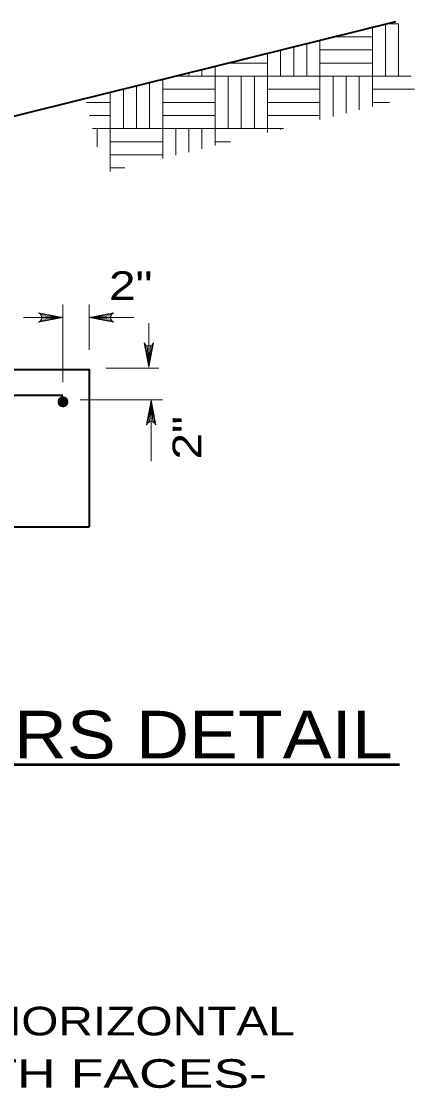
# Model space of a CAD drawing. Extents: x 394.95 to 401.96, y -76.51 to -66.78.
# Drawn here: x 400.292 to 401.117, y -69.196 to -66.946 of the extents above; entities that cross this region are included whole.
import ezdxf
from ezdxf.enums import TextEntityAlignment as Align

# ---------------------------------------------------------------- set-up
doc = ezdxf.new("R2010")
doc.units = 0
doc.header["$LTSCALE"] = 0.024
doc.linetypes.add('LONG_DASHED', pattern=[7.5, 6, -1.5])
for name, color, linetype, lineweight in [('1', 7, 'LONG_DASHED', 35), ('10', 7, 'Continuous', 13), ('13', 7, 'Continuous', 25), ('6', 7, 'Continuous', 13)]:
    doc.layers.add(name, color=color, linetype=linetype, lineweight=lineweight)
doc.layers.add('12', color=7, linetype='Continuous')

msp = doc.modelspace()

# ---------------------------------------------------------------- linework, layer by layer
at = {"layer": '1', "linetype": 'Continuous'}
for p, q in [((400.15918, -67.17381), (401.07785, -66.94648)), ((399.38918, -68.0064), (400.43418, -68.0064))]:
    msp.add_line(p, q, dxfattribs=at)
at = {"layer": '1', "linetype": 'Continuous', "lineweight": 13}
for p, q in [((400.69841, -67.06135), (400.69841, -67.04036)), ((400.61591, -67.06135), (400.61591, -67.06079))]:
    msp.add_line(p, q, dxfattribs=at)
at = {"layer": '1'}
msp.add_line((400.37918, -67.7314), (399.74668, -67.7314), dxfattribs=at)
at = {"layer": '1', "linetype": 'Continuous'}
msp.add_lwpolyline([(400.15918, -67.6764), (400.43418, -67.6764), (400.43418, -68.0064)], dxfattribs=at)
at = {"layer": '1', "lineweight": 13}
for points in [[(400.37644, -67.7349), (400.37965, -67.73433), (400.38343, -67.73546), (400.38741, -67.73895), (400.3888, -67.74228), (400.38884, -67.74629), (400.38675, -67.7508), (400.38375, -67.75345), (400.38042, -67.75428), (400.37665, -67.75417), (400.3734, -67.75259), (400.37118, -67.75055), (400.36978, -67.74746), (400.36912, -67.74401), (400.36998, -67.74079), (400.37158, -67.73806), (400.3742, -67.73591), (400.37644, -67.73497), (400.3823, -67.73502), (400.37527, -67.73542), (400.38367, -67.73546), (400.37343, -67.73602), (400.38482, -67.73622), (400.37295, -67.73666), (400.38547, -67.73674), (400.37227, -67.73719), (400.38627, -67.73743), (400.37162, -67.73779), (400.38687, -67.73795), (400.3713, -67.73839), (400.38711, -67.73847), (400.37085, -67.73883), (400.38768, -67.73895), (400.37061, -67.73916), (400.38784, -67.73943), (400.37043, -67.73967), (400.38813, -67.7398), (400.37022, -67.74007), (400.38836, -67.74023), (400.36966, -67.74064), (400.38853, -67.74064), (400.36957, -67.74124), (400.38865, -67.74096), (400.36945, -67.74192), (400.38884, -67.74159), (400.36921, -67.74269), (400.38889, -67.74213), (400.36933, -67.74236), (400.38912, -67.7426), (400.36918, -67.74317), (400.38909, -67.74314), (400.36909, -67.74361), (400.38921, -67.74353), (400.36905, -67.74405), (400.38921, -67.74389), (400.36918, -67.74469), (400.38921, -67.74436), (400.36909, -67.74517), (400.38933, -67.7449), (400.36901, -67.74442), (400.38921, -67.74533), (400.36912, -67.74557), (400.38928, -67.74578), (400.36918, -67.74602), (400.38909, -67.74626), (400.36925, -67.74642), (400.38896, -67.74666), (400.36942, -67.74694), (400.38889, -67.74702), (400.3695, -67.74739), (400.3888, -67.7475), (400.36981, -67.7479), (400.38872, -67.74795), (400.3699, -67.74834), (400.38853, -67.74826), (400.37002, -67.74882), (400.38829, -67.74867), (400.37034, -67.74927), (400.38816, -67.74915), (400.37058, -67.74968), (400.38789, -67.74959), (400.3707, -67.75003), (400.3876, -67.75011), (400.37102, -67.75043), (400.38735, -67.75048), (400.37134, -67.75075), (400.38692, -67.75096), (400.37182, -67.75128), (400.38635, -67.75144), (400.3723, -67.75184), (400.38575, -67.75196), (400.37299, -67.75252), (400.38531, -67.75235), (400.37423, -67.75316), (400.38487, -67.75292), (400.37387, -67.75292), (400.38419, -67.75328), (400.37468, -67.75345), (400.3833, -67.75372), (400.37531, -67.75376), (400.3823, -67.75408)], [(400.3823, -67.75408), (400.37873, -67.75452), (400.37343, -67.75107), (400.37019, -67.74397), (400.37495, -67.73594), (400.38191, -67.7351), (400.38728, -67.74127), (400.38728, -67.7479), (400.38391, -67.7528), (400.37833, -67.75387), (400.37203, -67.75059), (400.37431, -67.75248), (400.3703, -67.74196), (400.37406, -67.73615), (400.37961, -67.73454), (400.38371, -67.73639), (400.38716, -67.7404), (400.38869, -67.7437), (400.38687, -67.75016)]]:
    msp.add_lwpolyline(points, dxfattribs=at)
msp.add_circle((400.37918, -67.74445), 0.01031, dxfattribs=at)
at = {"layer": '10'}
for p, q in [((400.37918, -67.7032), (400.37918, -67.54021)), ((400.43418, -67.63515), (400.43418, -67.54021)), ((400.29668, -67.56771), (400.37918, -67.56771)), ((400.43418, -67.56771), (400.52855, -67.56771)), ((400.55951, -67.57941), (400.55951, -67.67194)), ((400.46942, -67.67409), (400.58059, -67.67409)), ((400.41501, -67.74039), (400.5877, -67.74039)), ((400.56425, -67.74125), (400.56441, -67.86873))]:
    msp.add_line(p, q, dxfattribs=at)
for points in [[(400.37918, -67.56771), (400.32792, -67.5773), (400.33186, -67.57458), (400.33391, -67.57115), (400.33449, -67.56771), (400.33391, -67.56427), (400.33186, -67.56083), (400.32792, -67.55809), (400.37918, -67.56771), (400.33186, -67.56083), (400.33391, -67.56427), (400.37918, -67.56771), (400.33449, -67.56771), (400.33391, -67.57115), (400.37918, -67.56771), (400.33186, -67.57458)], [(400.43418, -67.56771), (400.48544, -67.55809), (400.48149, -67.56083), (400.47946, -67.56427), (400.47886, -67.56771), (400.47946, -67.57115), (400.48149, -67.57458), (400.48544, -67.5773), (400.43418, -67.56771), (400.48149, -67.57458), (400.47946, -67.57115), (400.43418, -67.56771), (400.47886, -67.56771), (400.47946, -67.56427), (400.43418, -67.56771), (400.48149, -67.56083)], [(400.43418, -67.56771), (400.48544, -67.55809), (400.48149, -67.56083), (400.47946, -67.56427), (400.47886, -67.56771), (400.47946, -67.57115), (400.48149, -67.57458), (400.48544, -67.5773), (400.43418, -67.56771), (400.48149, -67.57458), (400.47946, -67.57115), (400.43418, -67.56771), (400.47886, -67.56771), (400.47946, -67.56427), (400.43418, -67.56771), (400.48149, -67.56083)], [(400.55951, -67.67194), (400.5499, -67.62068), (400.55264, -67.62464), (400.55607, -67.62666), (400.55951, -67.62725), (400.56295, -67.62666), (400.56639, -67.62464), (400.56911, -67.62068), (400.55951, -67.67194), (400.56639, -67.62464), (400.56295, -67.62666), (400.55951, -67.67194), (400.55951, -67.62725), (400.55607, -67.62666), (400.55951, -67.67194), (400.55264, -67.62464)], [(400.56425, -67.74125), (400.57385, -67.79252), (400.57112, -67.78856), (400.56769, -67.78652), (400.56425, -67.78594), (400.56081, -67.78652), (400.55737, -67.78856), (400.55464, -67.79252), (400.56425, -67.74125), (400.55737, -67.78856), (400.56081, -67.78652), (400.56425, -67.74125), (400.56425, -67.78594), (400.56769, -67.78652), (400.56425, -67.74125), (400.57112, -67.78856)]]:
    msp.add_lwpolyline(points, dxfattribs=at)
at = {"layer": '13', "lineweight": 53}
msp.add_line((398.77915, -68.50517), (401.08564, -68.50517), dxfattribs=at)
at = {"layer": '6'}
for p, q in [((401.05591, -67.06135), (401.05591, -66.95191)), ((401.05818, -66.95135), (401.08299, -66.95135)), ((401.08341, -67.06135), (401.08341, -66.95302)), ((400.94705, -66.97885), (401.02841, -66.97885)), ((401.02841, -67.06135), (401.02841, -66.95871)), ((400.86341, -67.06135), (400.86341, -66.99954)), ((400.89091, -67.06135), (400.89091, -66.99274)), ((400.80841, -67.06135), (400.80841, -67.01316)), ((400.83591, -67.06135), (400.83591, -67.00635)), ((400.91841, -67.00635), (401.02841, -67.00635)), ((400.67091, -67.06135), (400.67091, -67.04718)), ((400.72479, -67.03385), (400.80841, -67.03385)), ((400.91841, -67.03385), (401.02841, -67.03385)), ((400.58841, -67.17135), (400.58841, -67.06759)), ((400.64341, -67.06135), (400.64341, -67.05398)), ((400.69841, -67.17135), (400.69841, -67.06135)), ((400.72591, -67.17135), (400.72591, -67.06135)), ((400.75341, -67.17135), (400.75341, -67.06135)), ((400.78091, -67.17135), (400.78091, -67.06135)), ((400.80841, -67.17135), (400.80841, -67.06135)), ((400.94591, -67.14565), (400.94591, -67.06135)), ((400.97341, -67.13884), (400.97341, -67.06135)), ((401.00091, -67.13203), (401.00091, -67.06135)), ((401.02841, -67.12523), (401.02841, -67.06135)), ((401.02841, -67.06135), (401.11022, -67.06135)), ((400.50591, -67.17135), (400.50591, -67.08801)), ((400.53341, -67.17135), (400.53341, -67.08121)), ((400.56091, -67.17135), (400.56091, -67.0744)), ((400.58841, -67.08885), (400.69841, -67.08885)), ((400.80841, -67.08885), (400.91841, -67.08885)), ((401.02841, -67.08885), (401.11702, -67.08885)), ((400.47841, -67.17135), (400.47841, -67.09482)), ((400.42785, -67.11635), (400.47841, -67.11635)), ((400.58841, -67.11635), (400.69841, -67.11635)), ((400.80841, -67.11635), (400.91841, -67.11635)), ((401.02841, -67.11635), (401.06431, -67.11635)), ((400.43466, -67.14385), (400.47841, -67.14385)), ((400.58841, -67.14385), (400.69841, -67.14385)), ((400.80841, -67.14385), (400.91841, -67.14385)), ((400.44146, -67.17135), (400.47841, -67.17135)), ((400.45091, -67.20954), (400.45091, -67.17135)), ((400.47841, -67.26133), (400.47841, -67.17135)), ((400.47841, -67.17135), (400.58841, -67.17135)), ((400.58841, -67.23411), (400.58841, -67.17135)), ((400.58841, -67.17135), (400.69841, -67.17135)), ((400.61591, -67.22731), (400.61591, -67.17135)), ((400.64341, -67.22051), (400.64341, -67.17135)), ((400.67091, -67.2137), (400.67091, -67.17135)), ((400.69841, -67.2069), (400.69841, -67.17135)), ((400.69841, -67.17135), (400.80841, -67.17135)), ((400.80841, -67.17967), (400.80841, -67.17135)), ((400.80841, -67.17135), (400.84206, -67.17135)), ((400.83591, -67.17288), (400.83591, -67.17135)), ((400.47841, -67.19885), (400.58841, -67.19885)), ((400.69841, -67.19885), (400.73094, -67.19885)), ((400.47841, -67.22635), (400.58841, -67.22635)), ((400.47841, -67.25385), (400.50868, -67.25385))]:
    msp.add_line(p, q, dxfattribs=at)
for points in [[(400.91841, -67.15246), (400.91841, -67.06135), (400.91841, -66.98593)], [(400.61368, -67.06135), (400.69841, -67.06135), (400.80841, -67.06135)], [(400.80841, -67.06135), (400.91841, -67.06135), (401.02841, -67.06135)]]:
    msp.add_lwpolyline(points, dxfattribs=at)

# ---------------------------------------------------------------- texts
at = {"layer": '12'}
for s, height, width, p in [('2"', 0.06, 1.25, (400.52145, -67.53073)), ('DISPOSITION OF BARS DETAIL', 0.1, 1.15, (399.92606, -68.49266))]:
    msp.add_text(s, height=height, dxfattribs=dict(at, width=width)).set_placement(p, align=Align.CENTER)
at = {"layer": '12', "width": 1.25}
msp.add_text('2"', height=0.06, rotation=90, dxfattribs=at).set_placement((400.66922, -67.81993), align=Align.CENTER)
at = {"layer": '12'}
for s, width, p in [('NO.4 STRAIGHT BARS HORIZONTAL', 1.25, (399.12139, -69.07361)), ('@ 1\'-7" MAX  C/C BOTH FACES-', 1.4, (399.12139, -69.18361))]:
    msp.add_text(s, height=0.06, dxfattribs=dict(at, width=width)).set_placement(p)

doc.saveas('drawing.dxf')
